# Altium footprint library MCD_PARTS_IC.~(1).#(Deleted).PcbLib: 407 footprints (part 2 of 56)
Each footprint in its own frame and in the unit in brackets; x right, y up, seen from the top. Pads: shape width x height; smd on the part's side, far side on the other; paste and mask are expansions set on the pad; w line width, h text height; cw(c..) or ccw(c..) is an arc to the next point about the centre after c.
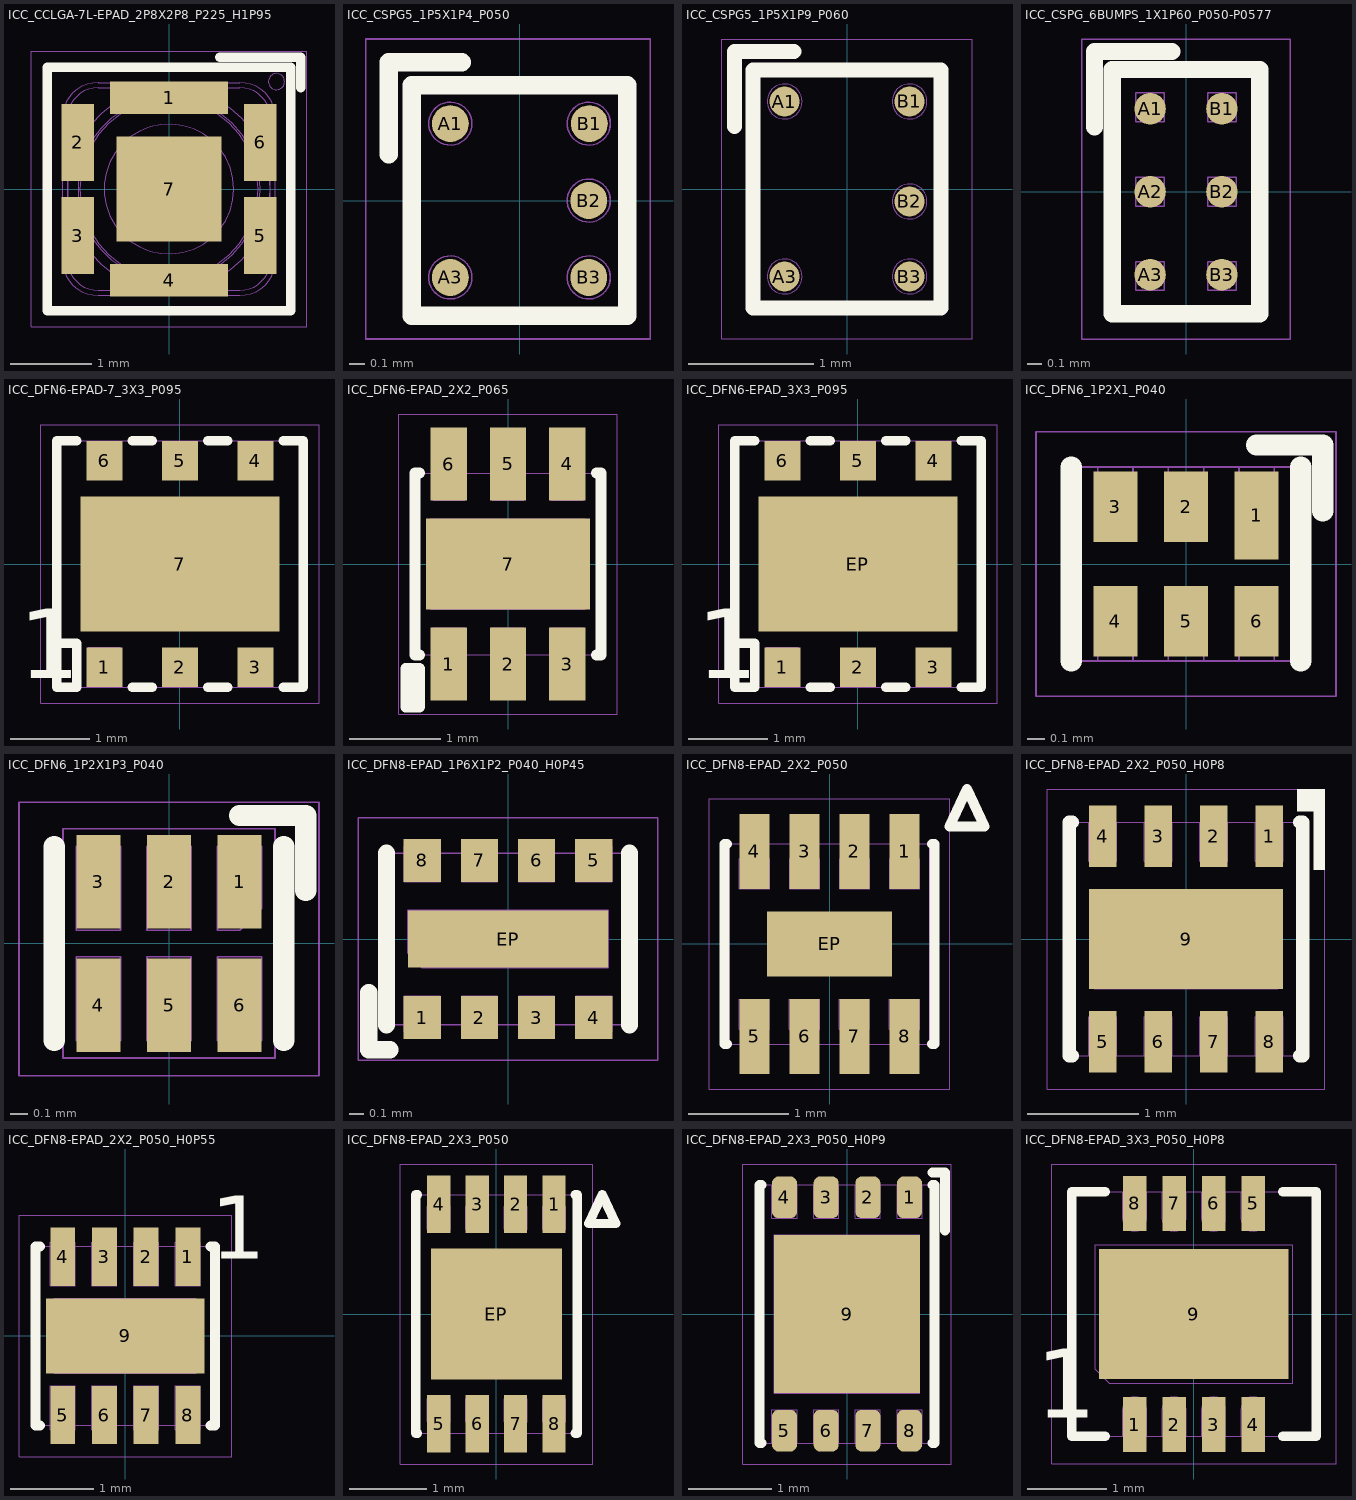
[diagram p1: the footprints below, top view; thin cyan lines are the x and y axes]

## ICC_CCLGA-7L-EPAD_2P8X2P8_P225_H1P95 [mm] "MCD-02515"
height 2.1
pads (7):
  rect 1.45x0.4 smd mask+0.05: 1(0,1.125) 4(0,-1.125)
  rect 0.4x0.95 smd mask+0.05: 2(-1.125,0.575) 3(-1.125,-0.575) 5(1.125,-0.575) 6(1.125,0.575)
  rect 1.3x1.3 smd mask+0.05: 7(0,0)
Top Overlay:
  lines w0.12: 0.625,1.625 1.625,1.625 1.625,1.25 ; -1.5,-1.5 -1.5,1.5 1.5,1.5 1.5,-1.5 -1.5,-1.5
M14-Top Assembly:
  circle w0.01: c0,0 r1.25
  circle w0.01: c0,0 r1.125
  circle w0.01: c0,0 r1.1
  circle w0.01: c0,0 r0.8
  circle w0.01: c1.325,1.325 r0.1
  lines w0.01: -1.5,-1.5 1.5,-1.5 1.5,1.5 -1.5,1.5 -1.5,-1.5 ; -1.312,-0.875 ccw(c-0.875,-0.875) -0.875,-1.312 0.875,-1.312 ccw(c0.875,-0.875) 1.312,-0.875 1.312,0.875 ccw(c0.875,0.875) 0.875,1.312 0,1.312 -0.875,1.312 ccw(c-0.875,0.875) -1.312,0.875 -1.312,-0.875 ; -1.25,-0.875 ccw(c-0.875,-0.875) -0.875,-1.25 0.875,-1.25 ccw(c0.875,-0.875) 1.25,-0.875 1.25,0.875 ccw(c0.875,0.875) 0.875,1.25 0,1.25 -0.875,1.25 ccw(c-0.875,0.875) -1.25,0.875 -1.25,-0.875
  text "'.Designator'" at -2,-0.5 h0.75
  text "1" at 0.325,1.007 h1
M16-Top Courtyard:
  lines w0.01: -1.7,-1.7 1.7,-1.7 1.7,1.7 -1.7,1.7 -1.7,-1.7
3D body: height 2.1, standoff 1.95, extent 0,-1.1 1.1,1.1
3D body: height 2.1, standoff 1.95, extent -1.1,-1.1 0,1.1
3D body: height 1.95, standoff 1.05, extent 0,-0.925 0.925,0.925
3D body: height 1.95, standoff 1.05, extent -0.925,-0.925 0,0.925
3D body: height 1.05, standoff 0.6, extent -1.25,-1.25 0,1.25
3D body: height 1.05, standoff 0.6, extent 0,-1.25 1.25,1.25
3D body: height 0.6, standoff 0.35, extent -1.312,-1.312 1.312,1.312
3D body: height 0.35, standoff 0, extent -1.5,-1.5 1.5,1.5

## ICC_CSPG5_1P5X1P4_P050 [mm] "MCD-03415"
height 0.68
pads (5):
  round 0.24 smd mask+0.05: A1(-0.45,0.5) A3(-0.45,-0.5) B1(0.453,0.5) B2(0.45,0) B3(0.45,-0.5)
Top Overlay:
  lines w0.12: -0.85,0.3 -0.85,0.9 -0.375,0.9 ; -0.7,-0.75 0.7,-0.75 0.7,0.75 -0.7,0.75 -0.7,-0.75
M14-Top Assembly:
  circle w0.01: c-0.45,0.5 r0.14
  circle w0.01: c0.45,0.5 r0.14
  circle w0.01: c0.45,0 r0.14
  circle w0.01: c-0.45,-0.5 r0.14
  circle w0.01: c0.45,-0.5 r0.14
  lines w0.01: -0.7,-0.75 0.7,-0.75 0.7,0.75 -0.7,0.75 -0.7,-0.75
  text "'.Designator'" at -2,-0.5 h0.75
  text "A1" at -0.675,0.375 h0.5
M16-Top Courtyard:
  lines w0.01: -1,-0.9 0.85,-0.9 0.85,1.05 -1,1.05 -1,-0.9
3D body: height 0.27, standoff -0.01, extent 0.319,-0.638 0.59,-0.362
3D body: height 0.27, standoff -0.01, extent -0.581,-0.638 -0.31,-0.362
3D body: height 0.27, standoff -0.01, extent -0.581,0.362 -0.31,0.638
3D body: height 0.27, standoff -0.01, extent 0.319,-0.138 0.59,0.138
3D body: height 0.27, standoff -0.01, extent 0.319,0.362 0.59,0.638
3D body: height 0.69, standoff 0.68, extent -0.599,0.35 -0.3,0.65
3D body: height 0.68, standoff 0.18, extent -0.7,-0.75 0.7,0.75

## ICC_CSPG5_1P5X1P9_P060 [mm]
height 0.68
pads (5):
  round 0.24 smd mask+0.05: A1(-0.5,0.7) A3(-0.5,-0.7) B1(0.5,0.7) B2(0.5,-0.1) B3(0.5,-0.7)
Top Overlay:
  lines w0.12: -0.9,0.5 -0.9,1.1 -0.425,1.1 ; -0.75,-0.95 -0.75,0.95 0.75,0.95 0.75,-0.95 -0.75,-0.95
M14-Top Assembly:
  circle w0.01: c0.5,-0.7 r0.14
  circle w0.01: c-0.5,-0.7 r0.14
  circle w0.01: c0.5,-0.1 r0.14
  circle w0.01: c0.5,0.7 r0.14
  circle w0.01: c-0.5,0.7 r0.14
  lines w0.01: -0.75,-0.95 -0.75,0.95 0.75,0.95 0.75,-0.95 -0.75,-0.95
  text "A1" at -0.675,0.525 h0.5
  text "'.Designator'" at -2,-0.5 h0.75
M16-Top Courtyard:
  lines w0.01: -1,-1.2 -1,1.2 1,1.2 1,-1.2 -1,-1.2
3D body: height 0.68, standoff 0.18, extent -0.75,-0.95 0.75,0.95
3D body: height 0.69, standoff 0.68, extent -0.649,0.55 -0.35,0.85
3D body: height 0.27, standoff -0.01, extent 0.365,0.562 0.637,0.838
3D body: height 0.27, standoff -0.01, extent 0.369,-0.238 0.64,0.038
3D body: height 0.27, standoff -0.01, extent -0.632,0.562 -0.36,0.838
3D body: height 0.27, standoff -0.01, extent -0.631,-0.838 -0.36,-0.562
3D body: height 0.27, standoff -0.01, extent 0.369,-0.838 0.64,-0.562

## ICC_CSPG_6BUMPS_1X1P60_P050-P0577 [mm] "MCD-03490"
height 0.68
pads (6):
  round 0.22 smd paste+0 mask+0: A1(-0.25,0.577) A2(-0.25,0) A3(-0.25,-0.577) B1(0.25,0.577) B2(0.25,0) B3(0.25,-0.577)
Top Overlay:
  lines w0.12: -0.637,0.45 -0.637,0.975 -0.1,0.975 ; -0.513,-0.85 -0.513,0.85 0.512,0.85 0.512,-0.85 -0.513,-0.85
M14-Top Assembly:
  lines w0.01: -0.513,-0.813 0.512,-0.813 0.512,0.813 -0.513,0.813 -0.513,-0.813 ; -0.35,-0.687 -0.15,-0.687 -0.15,-0.487 -0.35,-0.487 -0.35,-0.687 ; -0.35,-0.1 -0.15,-0.1 -0.15,0.1 -0.35,0.1 -0.35,-0.1 ; -0.35,0.487 -0.15,0.487 -0.15,0.687 -0.35,0.687 -0.35,0.487 ; 0.15,-0.687 0.35,-0.687 0.35,-0.487 0.15,-0.487 0.15,-0.687 ; 0.15,-0.1 0.35,-0.1 0.35,0.1 0.15,0.1 0.15,-0.1 ; 0.15,0.487 0.35,0.487 0.35,0.687 0.15,0.687 0.15,0.487
  text "'.Designator'" at -2,-0.5 h0.75
  text "A1" at -0.4,0.487 h0.3
  text "A2" at -0.4,-0.1 h0.3
  text "A3" at -0.4,-0.687 h0.3
  text "B3" at 0.1,-0.687 h0.3
  text "B2" at 0.1,-0.1 h0.3
  text "B1" at 0.125,0.487 h0.3
M16-Top Courtyard:
  lines w0.01: -0.725,-1.025 -0.725,1.062 0.725,1.062 0.725,-1.025 -0.725,-1.025
3D body: height 0.69, standoff 0.23, extent -0.513,-0.813 0.512,0.813
3D body: height 0.7, standoff 0.69, extent -0.351,0.487 -0.151,0.687
3D body: height 0.27, standoff -0.01, extent -0.39,0.437 -0.11,0.717
3D body: height 0.27, standoff -0.01, extent 0.11,0.437 0.39,0.717
3D body: height 0.27, standoff -0.01, extent -0.39,-0.14 -0.11,0.14
3D body: height 0.27, standoff -0.01, extent 0.11,-0.14 0.39,0.14
3D body: height 0.27, standoff -0.01, extent -0.39,-0.717 -0.11,-0.437
3D body: height 0.27, standoff -0.01, extent 0.11,-0.717 0.39,-0.437

## ICC_DFN6-EPAD-7_3X3_P095 [mm] "MCD-03655"
height 1
pads (7):
  rect 0.45x0.5 smd mask+0.05: 1(-0.95,-1.3) 2(0,-1.3) 3(0.95,-1.3) 4(0.95,1.3) 5(0,1.3) 6(-0.95,1.3)
  rect 2.5x1.7 smd mask+0.05: 7(0,0)
Top Overlay:
  lines w0.12: -1.55,-1 -1.3,-1 -1.3,-1.55 -1.55,-1.55 -1.55,1.55 -1.3,1.55 ; -0.6,-1.55 -0.35,-1.55 ; -0.6,1.55 -0.35,1.55 ; 0.35,-1.55 0.6,-1.55 ; 0.35,1.55 0.6,1.55 ; 1.3,-1.55 1.55,-1.55 1.55,1.55 1.3,1.55
  text "1" at -2.025,-1.725 h1.5
M14-Top Assembly:
  lines w0.01: -1.55,-1.55 -1.55,1.55 1.55,1.55 1.55,-1.55 -1.55,-1.55 ; -1.15,-1.45 -0.75,-1.45 -0.75,-1.05 -1.15,-1.05 -1.15,-1.45
  text "'.Designator'" at -2,-0.5 h0.75
M16-Top Courtyard:
  lines w0.01: -1.75,-1.75 -1.75,1.75 1.75,1.75 1.75,-1.75 -1.75,-1.75
3D body: height 1, standoff 0, extent -1.55,-1.55 1.55,1.55
3D body "DFN6-EPAD_3X3_P095.STEP": height 0.8, standoff 0, extent -1.5,-1.55 1.5,1.55

## ICC_DFN6-EPAD_2X2_P065 [mm] "MCD-01557"
height 1
pads (7):
  rect 0.4x0.8 smd mask+0.05: 1(-0.65,-1.1) 2(0,-1.1) 3(0.65,-1.1) 4(0.65,1.1) 5(0,1.1) 6(-0.65,1.1)
  rect 1.8x1 smd mask+0.05: 7(0,0)
Top Overlay:
  lines w0.12: -1.05,-1.575 -1.05,-1.15 ; -0.975,-1 -1,-1 -1.025,-1 -1.025,1 -0.975,1 ; 0.975,-1 1.025,-1 1.025,1 1,1 0.975,1 ; -1.125,-1.575 -0.975,-1.575 -0.975,-1.15 -1.125,-1.15 -1.125,-1.575
M14-Top Assembly:
  lines w0.01: -0.825,-1 -0.825,-0.7 -0.475,-0.7 -0.475,-1 ; -0.825,1 -0.825,0.7 -0.475,0.7 -0.475,1 ; -0.175,-1 -0.175,-0.7 0.175,-0.7 0.175,-1 ; -0.175,1 -0.175,0.7 0.175,0.7 0.175,1 ; 0.475,-1 0.475,-0.7 0.825,-0.7 0.825,-1 ; 0.475,1 0.475,0.7 0.825,0.7 0.825,1 ; -1,-1 -1,1 1,1 1,-1 -1,-1 ; -0.85,-0.5 0.85,-0.5 0.85,0.5 -0.85,0.5 -0.85,-0.5
  text "7" at -0.075,-0.15 h0.4
  text "6" at -0.725,0.725 h0.4
  text "5" at -0.075,0.725 h0.4
  text "4" at 0.55,0.725 h0.4
  text "3" at 0.575,-0.975 h0.4
  text "2" at -0.075,-0.975 h0.4
  text "1" at -0.7,-0.975 h0.4
  text "'.Designator'" at -2,-0.05 h0.75
M16-Top Courtyard:
  lines w0.01: -1.2,-1.65 1.2,-1.65 1.2,1.65 -1.2,1.65 -1.2,-1.65
3D body: height 1, standoff 0, extent -1,-1 1,1
3D body: height 1.01, standoff 1, extent -0.899,-0.9 -0.6,-0.6

## ICC_DFN6-EPAD_3X3_P095 [mm]
height 1
pads (7):
  rect 0.45x0.5 smd mask+0.05: 1(-0.95,-1.3) 2(0,-1.3) 3(0.95,-1.3) 4(0.95,1.3) 5(0,1.3) 6(-0.95,1.3)
  rect 2.5x1.7 smd mask+0.05: EP(0,0)
Top Overlay:
  lines w0.12: -1.55,-1 -1.3,-1 -1.3,-1.55 -1.55,-1.55 -1.55,1.55 -1.3,1.55 ; -0.6,-1.55 -0.35,-1.55 ; -0.6,1.55 -0.35,1.55 ; 0.35,-1.55 0.6,-1.55 ; 0.35,1.55 0.6,1.55 ; 1.3,-1.55 1.55,-1.55 1.55,1.55 1.3,1.55
  text "1" at -2.025,-1.725 h1.5
M14-Top Assembly:
  lines w0.01: -1.55,-1.55 -1.55,1.55 1.55,1.55 1.55,-1.55 -1.55,-1.55 ; -1.15,-1.45 -0.75,-1.45 -0.75,-1.05 -1.15,-1.05 -1.15,-1.45
  text "'.Designator'" at -2,-0.5 h0.75
M16-Top Courtyard:
  lines w0.01: -1.75,-1.75 -1.75,1.75 1.75,1.75 1.75,-1.75 -1.75,-1.75
3D body: height 1, standoff 0, extent -1.55,-1.55 1.55,1.55
3D body "DFN6-EPAD_3X3_P095.STEP": height 0.8, standoff 0, extent -1.5,-1.55 1.5,1.55

## ICC_DFN6_1P2X1_P040 [mm] "MCD-01477"
height 0.6
pads (6):
  rect 0.25x0.5 smd mask+0.038: 1(0.4,0.275)
  rect 0.25x0.4 smd mask+0.038: 2(0,0.325) 3(-0.4,0.325) 4(-0.4,-0.325) 5(0,-0.325) 6(0.4,-0.325)
Top Overlay:
  lines w0.12: -0.65,-0.55 -0.65,0.55 ; 0.4,0.675 0.775,0.675 0.775,0.3 ; 0.65,-0.55 0.65,0.55
M14-Top Assembly:
  lines w0.01: -0.5,-0.55 -0.5,-0.15 -0.3,-0.15 -0.3,-0.55 ; -0.5,0.55 -0.5,0.15 -0.3,0.15 -0.3,0.55 ; -0.1,-0.55 -0.1,-0.15 0.1,-0.15 0.1,-0.55 ; -0.1,0.55 -0.1,0.15 0.1,0.15 0.1,0.55 ; 0.3,-0.55 0.3,-0.15 0.5,-0.15 0.5,-0.55 ; 0.3,0.55 0.3,0.05 0.5,0.05 0.5,0.55 ; -0.65,-0.55 0.65,-0.55 0.65,0.55 -0.65,0.55 -0.65,-0.55
  text "6" at 0.3,-0.5 h0.5
  text "4" at -0.5,-0.5 h0.5
  text "3" at -0.5,0.175 h0.5
  text "1" at 0.35,0.125 h0.5
  text "'.Designator'" at -2,-0.5 h0.75
M16-Top Courtyard:
  lines w0.01: -0.85,-0.75 -0.85,0.75 0.85,0.75 0.85,-0.75 -0.85,-0.75
3D body: height 0.61, standoff 0.6, extent 0.251,0.125 0.55,0.425
3D body: height 0.6, standoff 0, extent -0.65,-0.55 0.65,0.55

## ICC_DFN6_1P2X1P3_P040 [mm] "MCD-02788"
height 0.5
pads (6):
  rect 0.25x0.53 smd mask+0.038: 1(0.4,0.35) 2(0,0.35) 3(-0.4,0.35) 4(-0.4,-0.35) 5(0,-0.35) 6(0.4,-0.35)
Top Overlay:
  lines w0.12: -0.65,-0.55 -0.65,0.55 ; 0.4,0.725 0.775,0.725 0.775,0.3 ; 0.65,-0.55 0.65,0.55
M14-Top Assembly:
  lines w0.01: -0.6,-0.65 0.6,-0.65 0.6,0.65 -0.6,0.65 -0.6,-0.65 ; -0.525,-0.55 -0.525,-0.075 -0.275,-0.075 -0.275,-0.55 -0.525,-0.55 ; -0.525,0.075 -0.275,0.075 -0.275,0.55 -0.525,0.55 -0.525,0.075 ; -0.125,-0.55 -0.125,-0.075 0.125,-0.075 0.125,-0.55 -0.125,-0.55 ; -0.125,0.075 0.125,0.075 0.125,0.55 -0.125,0.55 -0.125,0.075 ; 0.275,-0.55 0.275,-0.075 0.525,-0.075 0.525,-0.55 0.275,-0.55 ; 0.275,0.075 0.4,0.075 0.525,0.2 0.525,0.55 0.275,0.55 0.275,0.075
  text "6" at 0.3,-0.5 h0.5
  text "4" at -0.5,-0.5 h0.5
  text "3" at -0.5,0.175 h0.5
  text "1" at 0.35,0.125 h0.5
  text "'.Designator'" at 0,0 h0.75
M16-Top Courtyard:
  lines w0.01: -0.85,-0.75 -0.85,0.8 0.85,0.8 0.85,-0.75 -0.85,-0.75
3D body: height 0.51, standoff 0.5, extent 0.251,0.125 0.55,0.425
3D body: height 0.5, standoff 0, extent -0.6,-0.65 0.6,0.65

## ICC_DFN8-EPAD_1P6X1P2_P040_H0P45 [mm] "MCD-02937"
height 0.5
pads (9):
  rect 0.26x0.3 smd mask+0.035: 1(-0.6,-0.55) 2(-0.2,-0.55) 3(0.2,-0.55) 4(0.6,-0.55) 5(0.6,0.55) 6(0.2,0.55) 7(-0.2,0.55) 8(-0.6,0.55)
  rect 1.4x0.4 smd mask+0.05: EP(0,0)
Top Overlay:
  lines w0.12: -0.975,-0.375 -0.975,-0.775 -0.825,-0.775 ; -0.85,-0.6 -0.85,0.6 ; 0.85,-0.6 0.85,0.6
M14-Top Assembly:
  lines w0.01: -0.7,-0.1 -0.6,-0.2 0.7,-0.2 0.7,0.2 -0.7,0.2 -0.7,-0.1 ; -0.7,-0.1 -0.7,-0.1 ; -0.8,-0.6 -0.8,0.6 0.8,0.6 0.8,-0.6 -0.8,-0.6 ; -0.725,-0.65 -0.725,-0.4 -0.475,-0.4 -0.475,-0.65 -0.525,-0.65 -0.725,-0.65 ; -0.725,0.4 -0.725,0.65 -0.675,0.65 -0.475,0.65 -0.475,0.4 -0.725,0.4 ; -0.325,-0.65 -0.325,-0.4 -0.075,-0.4 -0.075,-0.65 -0.125,-0.65 -0.325,-0.65 ; -0.325,0.4 -0.325,0.65 -0.275,0.65 -0.075,0.65 -0.075,0.4 -0.325,0.4 ; 0.075,-0.65 0.075,-0.4 0.325,-0.4 0.325,-0.65 0.275,-0.65 0.075,-0.65 ; 0.075,0.4 0.075,0.65 0.125,0.65 0.325,0.65 0.325,0.4 0.075,0.4 ; 0.475,-0.65 0.475,-0.4 0.725,-0.4 0.725,-0.65 0.675,-0.65 0.475,-0.65 ; 0.475,0.4 0.475,0.65 0.525,0.65 0.725,0.65 0.725,0.4 0.475,0.4
  text "4" at 0.512,-0.575 h0.4
  text "1" at -0.647,-0.575 h0.4
  text "5" at 0.515,0.329 h0.4
  text "8" at -0.684,0.329 h0.4
  text "9" at -0.084,-0.121 h0.4
  text "'.Designator'" at 0,0 h0.75
M16-Top Courtyard:
  lines w0.01: -1.05,-0.85 1.05,-0.85 1.05,0.85 -1.05,0.85 -1.05,-0.85
3D body: height 0.5, standoff 0.05, extent -0.8,-0.6 0.8,0.6
3D body: height 0.05, standoff 0, extent 0.475,-0.6 0.725,-0.4
3D body: height 0.15, standoff 0, extent 0.475,-0.65 0.725,-0.6
3D body: height 0.05, standoff 0, extent 0.075,-0.6 0.325,-0.4
3D body: height 0.15, standoff 0, extent 0.075,-0.65 0.325,-0.6
3D body: height 0.05, standoff 0, extent -0.325,-0.6 -0.075,-0.4
3D body: height 0.15, standoff 0, extent -0.325,-0.65 -0.075,-0.6
3D body: height 0.05, standoff 0, extent -0.725,-0.6 -0.475,-0.4
3D body: height 0.15, standoff 0, extent -0.725,-0.65 -0.475,-0.6
3D body: height 0.05, standoff 0, extent 0.475,0.4 0.725,0.6
3D body: height 0.15, standoff 0, extent 0.475,0.6 0.725,0.65
3D body: height 0.05, standoff 0, extent 0.075,0.4 0.325,0.6
3D body: height 0.15, standoff 0, extent 0.075,0.6 0.325,0.65
3D body: height 0.05, standoff 0, extent -0.325,0.4 -0.075,0.6
3D body: height 0.15, standoff 0, extent -0.325,0.6 -0.075,0.65
3D body: height 0.05, standoff 0, extent -0.7,-0.2 0.7,0.2
3D body: height 0.05, standoff 0, extent -0.725,0.4 -0.475,0.6
3D body: height 0.15, standoff 0, extent -0.725,0.6 -0.475,0.65
3D body: height 0.51, standoff 0.5, extent -0.699,-0.5 -0.5,-0.301

## ICC_DFN8-EPAD_2X2_P050 [mm] "MCD-01753"
height 0.9
pads (9):
  rect 0.3x0.75 smd mask+0.05: 1(0.75,0.925) 2(0.25,0.925) 3(-0.25,0.925) 4(-0.75,0.925) 5(-0.75,-0.925) 6(-0.25,-0.925) 7(0.25,-0.925) 8(0.75,-0.925)
  rect 1.25x0.65 smd mask+0.05: EP(0,0)
Top Overlay:
  lines w0.1: -1.025,-1 -1.05,-1 -1.05,1 -1.025,1 ; 1.025,-1 1.05,-1 1.05,1 1.025,1 ; 1.2,1.175 1.55,1.175 1.375,1.55 1.2,1.175
M14-Top Assembly:
  lines w0.01: -1,-1 -1,1 1,1 1,-1 -1,-1 ; -0.9,-0.85 -0.6,-0.85 -0.6,-0.55 -0.9,-0.55 -0.9,-0.85 ; -0.9,0.55 -0.9,0.85 -0.6,0.85 -0.6,0.55 -0.9,0.55 ; -0.6,-0.3 -0.6,0.3 0.6,0.3 0.6,-0.3 -0.6,-0.3 ; -0.4,-0.85 -0.1,-0.85 -0.1,-0.55 -0.4,-0.55 -0.4,-0.85 ; -0.4,0.55 -0.1,0.55 -0.1,0.85 -0.4,0.85 -0.4,0.55 ; 0.1,-0.85 0.4,-0.85 0.4,-0.55 0.1,-0.55 0.1,-0.85 ; 0.1,0.55 0.4,0.55 0.4,0.85 0.1,0.85 0.1,0.55 ; 0.6,-0.85 0.9,-0.85 0.9,-0.55 0.6,-0.55 0.6,-0.85 ; 0.6,0.55 0.9,0.55 0.9,0.85 0.6,0.85 0.6,0.55
  text "8" at 0.65,-0.875 h0.5
  text "5" at -0.85,-0.875 h0.5
  text "EP" at -0.275,-0.175 h0.5
  text "4" at -0.875,0.55 h0.5
  text "1" at 0.675,0.55 h0.5
  text "'.Designator'" at -2,-0.5 h0.75
M16-Top Courtyard:
  lines w0.01: -1.2,-1.45 1.2,-1.45 1.2,1.45 -1.2,1.45 -1.2,-1.45
3D body: height 0.6, standoff 0, extent -1.05,-1 1.05,1
3D body "User Library-DFN8-2x2.STEP": height 0.95, standoff -0.05, extent -1,-1.01 1,1.01

## ICC_DFN8-EPAD_2X2_P050_H0P8 [mm]
height 0.8
pads (9):
  rect 0.25x0.55 smd mask+0.05: 1(0.75,0.925) 2(0.25,0.925) 3(-0.25,0.925) 4(-0.75,0.925) 5(-0.75,-0.925) 6(-0.25,-0.925) 7(0.25,-0.925) 8(0.75,-0.925)
  rect 1.75x0.9 smd mask+0.05: 9(0,0)
Top Overlay:
  region: 1,1.35 1.25,1.35 1.25,0.625 1.15,0.625 1.15,1.15 1,1.15
  lines w0.12: -1.025,-1.05 -1.05,-1.05 -1.05,1.05 -1.025,1.05 ; 1.025,-1.05 1.05,-1.05 1.05,1.05 1.025,1.05
M14-Top Assembly:
  lines w0.01: -0.875,-1.05 -0.875,-0.7 -0.625,-0.7 -0.625,-1.05 ; -0.875,1.05 -0.875,0.7 -0.625,0.7 -0.625,1.05 ; -0.375,-1.05 -0.375,-0.7 -0.125,-0.7 -0.125,-1.05 ; -0.375,1.05 -0.375,0.7 -0.125,0.7 -0.125,1.05 ; 0.125,-1.05 0.125,-0.7 0.375,-0.7 0.375,-1.05 ; 0.125,1.05 0.125,0.7 0.375,0.7 0.375,1.05 ; 0.625,-1.05 0.625,-0.7 0.875,-0.7 0.875,-1.05 ; 0.625,1.05 0.625,0.7 0.875,0.7 0.875,1.05 ; -1.05,-1.05 1.05,-1.05 1.05,1.05 -1.05,1.05 -1.05,-1.05 ; -0.825,-0.45 -0.825,0.45 0.825,0.45 0.825,-0.45 -0.825,-0.45
  text "'.Designator'" at -2,0 h0.75
  text "1" at 0.675,0.65 h0.5
  text "4" at -0.875,0.65 h0.5
  text "9" at -0.1,-0.15 h0.5
  text "5" at -0.85,-0.975 h0.5
  text "8" at 0.65,-0.975 h0.5
M16-Top Courtyard:
  lines w0.01: -1.25,-1.35 -1.25,1.35 1.25,1.35 1.25,-1.35 -1.25,-1.35
3D body "LS0505EVD22.stp": height 0.8, standoff 0, extent -1,-1.05 1,1.05

## ICC_DFN8-EPAD_2X2_P050_H0P55 [mm] "MCD-01890"
height 0.6
pads (9):
  rect 0.3x0.7 smd mask+0.05: 1(0.75,0.95) 2(0.25,0.95) 3(-0.25,0.95) 4(-0.75,0.95) 5(-0.75,-0.95) 6(-0.25,-0.95) 7(0.25,-0.95) 8(0.75,-0.95)
  rect 1.9x0.9 smd mask+0.05: 9(0,0)
Top Overlay:
  lines w0.12: -1.025,-1.075 -1.075,-1.075 -1.075,1.075 -1.025,1.075 ; 1.025,-1.075 1.075,-1.075 1.075,1.075 1.025,1.075
  text "1" at 1.025,0.675 h1.3
M14-Top Assembly:
  lines w0.01: -0.9,-1.075 -0.6,-1.075 ; -0.9,-1.075 -0.9,-0.6 -0.6,-0.6 -0.6,-1.075 ; -0.9,-1.075 -0.9,-1.125 -0.6,-1.125 -0.6,-1.075 ; -0.9,1.075 -0.9,0.6 -0.6,0.6 -0.6,1.075 ; -0.9,1.075 -0.6,1.075 ; -0.9,1.075 -0.9,1.125 -0.6,1.125 -0.6,1.075 ; -0.4,-1.075 -0.1,-1.075 ; -0.4,-1.075 -0.4,-0.6 -0.1,-0.6 -0.1,-1.075 ; -0.4,-1.075 -0.4,-1.125 -0.1,-1.125 -0.1,-1.075 ; -0.4,1.075 -0.1,1.075 ; -0.4,1.075 -0.4,0.6 -0.1,0.6 -0.1,1.075 ; -0.4,1.075 -0.4,1.125 -0.1,1.125 -0.1,1.075 ; 0.1,-1.075 0.4,-1.075 ; 0.1,-1.075 0.1,-0.6 0.4,-0.6 0.4,-1.075 ; 0.1,-1.075 0.1,-1.125 0.4,-1.125 0.4,-1.075 ; 0.1,1.075 0.4,1.075 ; 0.1,1.075 0.1,0.6 0.4,0.6 0.4,1.075 ; 0.1,1.075 0.1,1.125 0.4,1.125 0.4,1.075 ; 0.6,-1.075 0.9,-1.075 ; 0.6,-1.075 0.6,-0.6 0.9,-0.6 0.9,-1.075 ; 0.6,-1.075 0.6,-1.125 0.9,-1.125 0.9,-1.075 ; 0.6,1.075 0.9,1.075 ; 0.6,1.075 0.6,0.6 0.9,0.6 0.9,1.075 ; 0.6,1.075 0.6,1.125 0.9,1.125 0.9,1.075 ; -1.075,-1.075 -1.075,1.075 1.075,1.075 1.075,-1.075 -1.075,-1.075 ; -0.85,-0.45 -0.85,0.45 0.85,0.45 0.85,-0.45 -0.85,-0.45
  text "8" at 0.65,-0.975 h0.5
  text "5" at -0.85,-0.975 h0.5
  text "9" at -0.1,-0.15 h0.5
  text "4" at -0.875,0.65 h0.5
  text "1" at 0.675,0.65 h0.5
  text "'.Designator'" at -2,0.025 h0.75
M16-Top Courtyard:
  lines w0.01: -1.275,-1.45 1.275,-1.45 1.275,1.45 -1.275,1.45 -1.275,-1.45
3D body: height 0.05, standoff 0, extent -0.85,-0.45 0.85,0.45
3D body: height 0.05, standoff 0, extent 0.6,-1.075 0.9,-0.6
3D body: height 0.05, standoff 0, extent 0.1,-1.075 0.4,-0.6
3D body: height 0.05, standoff 0, extent -0.4,-1.075 -0.1,-0.6
3D body: height 0.05, standoff 0, extent -0.9,-1.075 -0.6,-0.6
3D body: height 0.05, standoff 0, extent 0.6,0.6 0.9,1.075
3D body: height 0.05, standoff 0, extent 0.1,0.6 0.4,1.075
3D body: height 0.05, standoff 0, extent -0.4,0.6 -0.1,1.075
3D body: height 0.05, standoff 0, extent -0.9,0.6 -0.6,1.075
3D body: height 0.15, standoff 0, extent -0.9,1.075 -0.6,1.125
3D body: height 0.15, standoff 0, extent -0.4,1.075 -0.1,1.125
3D body: height 0.15, standoff 0, extent 0.1,1.075 0.4,1.125
3D body: height 0.15, standoff 0, extent 0.6,1.075 0.9,1.125
3D body: height 0.15, standoff 0, extent 0.6,-1.125 0.9,-1.075
3D body: height 0.15, standoff 0, extent 0.1,-1.125 0.4,-1.075
3D body: height 0.15, standoff 0, extent -0.4,-1.125 -0.1,-1.075
3D body: height 0.15, standoff 0, extent -0.9,-1.125 -0.6,-1.075
3D body: height 0.61, standoff 0.6, extent 0.552,0.551 0.95,0.95
3D body: height 0.6, standoff 0.05, extent -1.075,-1.075 1.075,1.075

## ICC_DFN8-EPAD_2X3_P050 [mm]
height 0.6
pads (9):
  rect 0.3x0.75 smd mask+0.05: 1(0.75,1.425) 2(0.25,1.425) 3(-0.25,1.425) 4(-0.75,1.425) 5(-0.75,-1.425) 6(-0.25,-1.425) 7(0.25,-1.425) 8(0.75,-1.425)
  rect 1.7x1.7 smd mask+0.05: EP(0,0)
Top Overlay:
  lines w0.12: -1.025,-1.55 -1.05,-1.55 -1.05,1.55 -1.025,1.55 ; 1.025,-1.55 1.05,-1.55 1.05,1.55 1.025,1.55 ; 1.2,1.175 1.55,1.175 1.375,1.55 1.2,1.175
M14-Top Assembly:
  lines w0.01: -1.05,-1.55 -1.05,1.55 1.05,1.55 1.05,-1.55 -1.05,-1.55 ; -0.9,-1.4 -0.6,-1.4 -0.6,-1.1 -0.9,-1.1 -0.9,-1.4 ; -0.9,1.1 -0.9,1.4 -0.6,1.4 -0.6,1.1 -0.9,1.1 ; -0.8,-0.8 -0.8,0.8 0.8,0.8 0.8,-0.8 -0.8,-0.8 ; -0.4,-1.4 -0.1,-1.4 -0.1,-1.1 -0.4,-1.1 -0.4,-1.4 ; -0.4,1.1 -0.1,1.1 -0.1,1.4 -0.4,1.4 -0.4,1.1 ; 0.1,-1.4 0.4,-1.4 0.4,-1.1 0.1,-1.1 0.1,-1.4 ; 0.1,1.1 0.4,1.1 0.4,1.4 0.1,1.4 0.1,1.1 ; 0.6,-1.4 0.9,-1.4 0.9,-1.1 0.6,-1.1 0.6,-1.4 ; 0.6,1.1 0.9,1.1 0.9,1.4 0.6,1.4 0.6,1.1
  text "8" at 0.65,-1.425 h0.5
  text "5" at -0.85,-1.425 h0.5
  text "EP" at -0.275,-0.175 h0.5
  text "4" at -0.875,1.1 h0.5
  text "1" at 0.675,1.1 h0.5
  text "'.Designator'" at -2,0 h0.75
M16-Top Courtyard:
  lines w0.01: -1.25,-1.95 1.25,-1.95 1.25,1.95 -1.25,1.95 -1.25,-1.95
3D body: height 0.61, standoff 0.6, extent 0.552,1.051 0.95,1.45
3D body: height 0.6, standoff 0, extent -1.05,-1.55 1.05,1.55
3D body "DFN-8-2X3_P050.STEP": height 0.9, standoff 0, extent -1,-1.52 1,1.52

## ICC_DFN8-EPAD_2X3_P050_H0P9 [mm] "MCD-02312"
height 1
pads (9):
  rrect50% 0.3x0.5 smd mask+0.05: 1(0.75,1.4) 2(0.25,1.4) 3(-0.25,1.4) 4(-0.75,1.4) 5(-0.75,-1.4) 6(-0.25,-1.4) 7(0.25,-1.4) 8(0.75,-1.4)
  rect 1.75x1.9 smd mask+0.05: 9(0,0)
Top Overlay:
  lines w0.12: -1.025,-1.55 -1.05,-1.55 -1.05,1.55 -1.025,1.55 ; 1.025,-1.55 1.05,-1.55 1.05,1.55 1.025,1.55 ; 1.175,1 1.175,1.7 ; 1.175,1.7 1.025,1.7 1.175,1.7
M14-Top Assembly:
  lines w0.01: -0.9,-1.55 -0.9,-1.15 -0.6,-1.15 -0.6,-1.55 ; -0.9,1.55 -0.9,1.15 -0.6,1.15 -0.6,1.55 ; -0.4,-1.55 -0.4,-1.15 -0.1,-1.15 -0.1,-1.55 ; -0.4,1.55 -0.4,1.15 -0.1,1.15 -0.1,1.55 ; 0.1,-1.55 0.1,-1.15 0.4,-1.15 0.4,-1.55 ; 0.1,1.55 0.1,1.15 0.4,1.15 0.4,1.55 ; 0.6,-1.55 0.6,-1.15 0.9,-1.15 0.9,-1.55 ; 0.6,1.55 0.6,1.15 0.9,1.15 0.9,1.55 ; -1.05,-1.55 1.05,-1.55 1.05,1.55 -1.05,1.55 -1.05,-1.55 ; -0.875,-0.95 0.875,-0.95 0.875,0.95 -0.875,0.95 -0.875,-0.95
  text "'.Designator'" at -2,-0.5 h0.75
  text "1" at 0.675,1.2 h0.5
  text "4" at -0.875,1.2 h0.5
  text "9" at -0.1,-0.175 h0.5
  text "5" at -0.85,-1.5 h0.5
  text "8" at 0.65,-1.5 h0.5
M16-Top Courtyard:
  lines w0.01: -1.25,-1.8 -1.25,1.8 1.25,1.8 1.25,-1.8 -1.25,-1.8
3D body "DFN-8-2X3_P050.STEP": height 0.9, standoff 0, extent -1,-1.52 1,1.52

## ICC_DFN8-EPAD_3X3_P050_H0P8 [mm] "MCD-02680"
height 0.8
pads (9):
  rect 0.3x0.7 smd mask+0.05: 1(-0.75,-1.4) 2(-0.25,-1.4) 3(0.25,-1.4) 4(0.75,-1.4) 5(0.75,1.4) 6(0.25,1.4) 7(-0.25,1.4) 8(-0.75,1.4)
  rect 2.4x1.65 smd mask+0.05: 9(0,0)
Top Overlay:
  lines w0.12: -1.125,-1.55 -1.55,-1.55 -1.55,1.55 -1.125,1.55 ; 1.125,-1.55 1.55,-1.55 1.55,1.55 1.125,1.55
  text "1" at -2,-1.6 h1.5
M14-Top Assembly:
  lines w0.01: -0.9,-1.55 -0.9,-1.2 cw(c-0.75,-1.2) -0.75,-1.05 cw(c-0.75,-1.2) -0.6,-1.2 -0.6,-1.55 ; -0.9,1.55 -0.9,1.2 ccw(c-0.75,1.2) -0.75,1.05 ccw(c-0.75,1.2) -0.6,1.2 -0.6,1.55 ; -0.4,-1.55 -0.4,-1.2 cw(c-0.25,-1.2) -0.25,-1.05 cw(c-0.25,-1.2) -0.1,-1.2 -0.1,-1.55 ; -0.4,1.55 -0.4,1.2 ccw(c-0.25,1.2) -0.25,1.05 ccw(c-0.25,1.2) -0.1,1.2 -0.1,1.55 ; 0.1,-1.55 0.1,-1.2 cw(c0.25,-1.2) 0.25,-1.05 cw(c0.25,-1.2) 0.4,-1.2 0.4,-1.55 ; 0.1,1.55 0.1,1.2 ccw(c0.25,1.2) 0.25,1.05 ccw(c0.25,1.2) 0.4,1.2 0.4,1.55 ; 0.6,-1.55 0.6,-1.2 cw(c0.75,-1.2) 0.75,-1.05 cw(c0.75,-1.2) 0.9,-1.2 0.9,-1.55 ; 0.6,1.55 0.6,1.2 ccw(c0.75,1.2) 0.75,1.05 ccw(c0.75,1.2) 0.9,1.2 0.9,1.55 ; -1.55,-1.55 1.55,-1.55 1.55,1.55 -1.55,1.55 -1.55,-1.55 ; -1.25,-0.7 -1.25,0.875 1.25,0.875 1.25,-0.875 -1.075,-0.875 -1.25,-0.7
  text "1" at -0.825,-1.5 h0.5
  text "4" at 0.625,-1.5 h0.5
  text "9" at -0.1,-0.125 h0.5
  text "5" at 0.65,1.2 h0.5
  text "8" at -0.85,1.2 h0.5
  text "'.Designator'" at -2,0 h0.75
M16-Top Courtyard:
  lines w0.01: -1.8,-1.9 1.8,-1.9 1.8,1.9 -1.8,1.9 -1.8,-1.9
3D body "User Library-My-DFN-8-3x3-0_5.STEP": height 0.8, standoff 0, extent -1.55,-1.56 1.55,1.56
